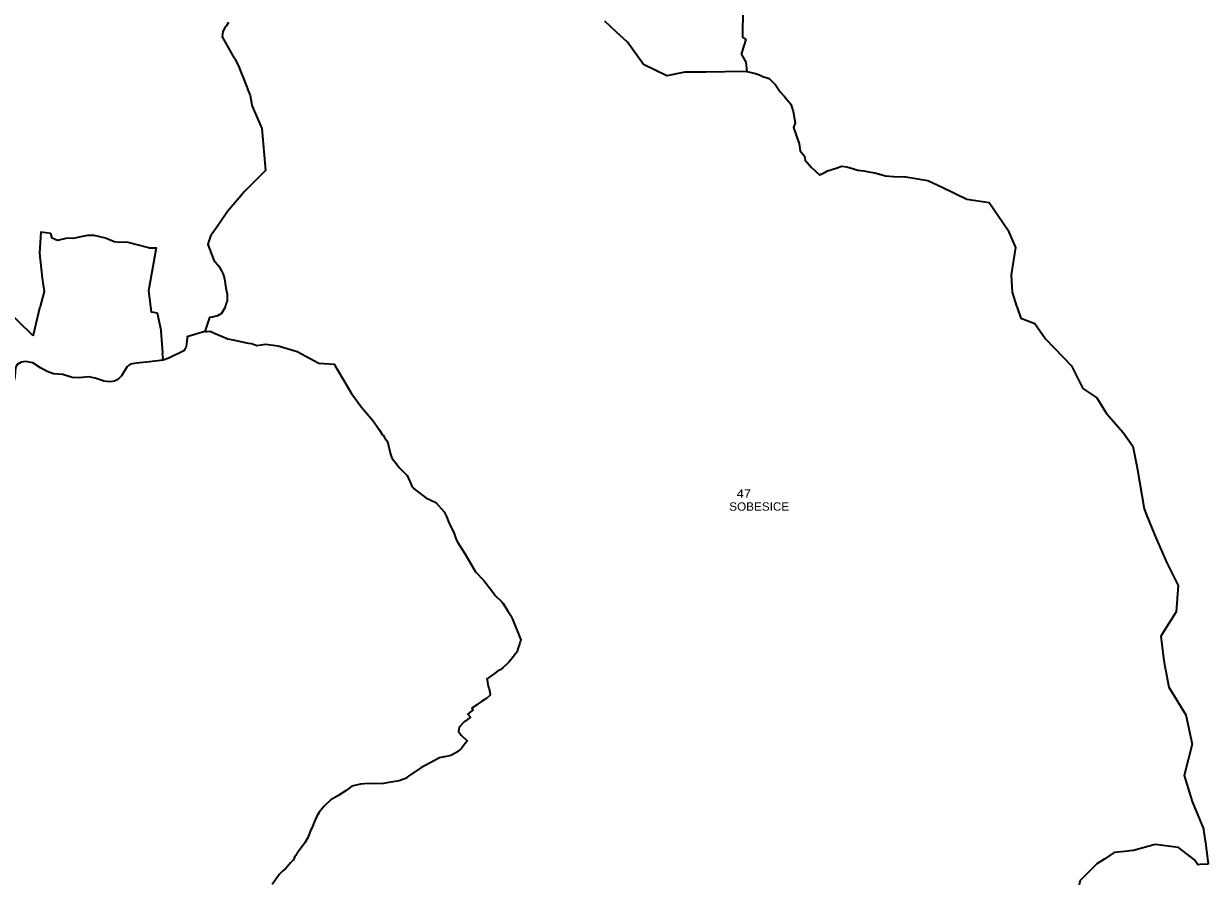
# Model space of a CAD drawing. Extents: x -610940 to -588976, y -1170376 to -1149800.
# Drawn here: x -598167 to -594623, y -1154902 to -1152351 of the extents above; entities that cross this region are included whole.
import ezdxf

# ---------------------------------------------------------------- set-up
doc = ezdxf.new("R2010")
doc.units = 0
doc.header["$LTSCALE"] = 10
doc.layers.add('54', color=7, linetype='Continuous', lineweight=35)
doc.layers.add('55', color=7, linetype='Continuous')
doc.layers.add('56', color=7, linetype='Continuous')

msp = doc.modelspace()

# ---------------------------------------------------------------- linework, layer by layer
at = {"layer": '54'}
for p, q in [((-598106.27, -1153152.22), (-598117.31, -1153197.4)), ((-598138.13, -1153282.6), (-598117.31, -1153197.4)), ((-598138.68, -1153284.83), (-598138.13, -1153282.6)), ((-597752.83, -1153338.08), (-597751.22, -1153349.79)), ((-597750.15, -1153357.57), (-597751.22, -1153349.79))]:
    msp.add_line(p, q, dxfattribs=at)
for points in [[(-596015.77, -1152305.6), (-596016.42, -1152391.27), (-596006.07, -1152398.68), (-596017.94, -1152436.65), (-596019.02, -1152439.81), (-596019.77, -1152443.4), (-596005.95, -1152466.61), (-596003.52, -1152494.58), (-596068.84, -1152495.06), (-596125.45, -1152495.82), (-596189.2, -1152496.63), (-596242.89, -1152507.33), (-596312.34, -1152473.24), (-596360.45, -1152406.2), (-596394.58, -1152375.26), (-596428.18, -1152343.88)], [(-597554.46, -1152347.09), (-597561.53, -1152358.53), (-597564.82, -1152363.84), (-597571.3, -1152374.31), (-597573.43, -1152390.4), (-597537.04, -1152454.25), (-597535.67, -1152456.67), (-597524.14, -1152477.31), (-597515.92, -1152498.31), (-597510.53, -1152512.06), (-597502.25, -1152533.21), (-597499.65, -1152539.87), (-597498.54, -1152542.68), (-597496.08, -1152548.98), (-597489.32, -1152566.23), (-597485.52, -1152588.28), (-597484.35, -1152595.14), (-597483.7, -1152597.78), (-597454.53, -1152664.27), (-597443.68, -1152790.87), (-597505.89, -1152852.62), (-597557.05, -1152912.73), (-597580.62, -1152946.74), (-597607.81, -1152986.56), (-597613.82, -1153005.03), (-597616.01, -1153011.86), (-597597.7, -1153058.74)], [(-596003.52, -1152494.58), (-595977.76, -1152500.16), (-595965.5, -1152504.52), (-595955.08, -1152509.58), (-595936.58, -1152514.66), (-595917.44, -1152533.82), (-595903.92, -1152555.48), (-595892.16, -1152567.64), (-595871.6, -1152591.92), (-595869.9, -1152597.7), (-595864.78, -1152614.14), (-595858.84, -1152647.78), (-595863.94, -1152661.92), (-595846.74, -1152710.98), (-595843.48, -1152731.8), (-595830.44, -1152747.62), (-595828.74, -1152759.98), (-595810.42, -1152781.02), (-595785.22, -1152803.96), (-595780.6, -1152801.4), (-595767.54, -1152794.02), (-595761.72, -1152790.92), (-595738.78, -1152783.96), (-595718.78, -1152777), (-595704.16, -1152779.84), (-595687.06, -1152784.2), (-595671.36, -1152789.26), (-595652.9, -1152791.06), (-595638.32, -1152794.76), (-595620.3, -1152797.16), (-595588.68, -1152806.1), (-595564.54, -1152808.78), (-595530.58, -1152809.5), (-595527.6, -1152809.82), (-595461.76, -1152820.26), (-595416.6, -1152840.9), (-595345.18, -1152876.14), (-595278.8, -1152885.94), (-595222.18, -1152968.33), (-595199.99, -1153021.25)], [(-597793.09, -1153021.92), (-597858.78, -1153004.63), (-597879.33, -1153006.04), (-597896.69, -1153004.13), (-597921.98, -1152992.94), (-597955.91, -1152985), (-597976.47, -1152984.72), (-598020.42, -1152993.75), (-598036.98, -1152993.06), (-598066.18, -1152999.88), (-598081.73, -1152992.62), (-598085.51, -1152978.76), (-598115.9, -1152974.94), (-598119.52, -1153038.03)], [(-598119.52, -1153038.03), (-598112.01, -1153113.03), (-598106.27, -1153152.22)], [(-597793.09, -1153021.92), (-597770.49, -1153021.36), (-597794.04, -1153150.2)], [(-595199.99, -1153021.25), (-595212.42, -1153102.38), (-595210.04, -1153154.18), (-595196.12, -1153196.52), (-595194.68, -1153200.5), (-595183.98, -1153232.74), (-595141.35, -1153247.94), (-595110.02, -1153294.1), (-595032.06, -1153374.88), (-595019.76, -1153399.22), (-594998.11, -1153442.37), (-594988.96, -1153448.84), (-594985.98, -1153450.76), (-594956.04, -1153470.7), (-594927.74, -1153517.4), (-594877.22, -1153574.7), (-594848.16, -1153615.24), (-594835.26, -1153680), (-594814.92, -1153802.58), (-594809.78, -1153815.58), (-594808.68, -1153818.42), (-594782.1, -1153884.74), (-594746.68, -1153964.64), (-594713.04, -1154032.5), (-594718.54, -1154110.96), (-594764.5, -1154183.75), (-594757, -1154249.24), (-594751.38, -1154280.6), (-594750.84, -1154283.64), (-594747.9, -1154299.2), (-594741.12, -1154336.37), (-594690.38, -1154418.8), (-594670.74, -1154507.01), (-594694.73, -1154601.21), (-594670.95, -1154678.66), (-594637.4, -1154760.24), (-594636.78, -1154763.08), (-594631.94, -1154796.18), (-594630.98, -1154801.12), (-594622.71, -1154865.58)], [(-597597.7, -1153058.74), (-597583.34, -1153077.07), (-597574.76, -1153090.52), (-597570.52, -1153100.56), (-597566.43, -1153114.14), (-597562.72, -1153142.17), (-597558.62, -1153160.17), (-597557.77, -1153181.44), (-597561.61, -1153186.99), (-597564.35, -1153199.22), (-597575.35, -1153217.89), (-597586.96, -1153225.77), (-597602.64, -1153228.96), (-597610.85, -1153230.14), (-597625.34, -1153272.57), (-597632.29, -1153274.6), (-597664.98, -1153284.15), (-597668.65, -1153285.21), (-597677.47, -1153287.77), (-597678.41, -1153295.55), (-597678.64, -1153297.43), (-597679.19, -1153302.27), (-597680.01, -1153309.36), (-597680.87, -1153316.94), (-597683.21, -1153321.34), (-597683.69, -1153322.23), (-597684.23, -1153323.22), (-597687.6, -1153329.58), (-597732.49, -1153351.48), (-597735.85, -1153352.58), (-597750.15, -1153357.57)], [(-597794.04, -1153150.2), (-597785.83, -1153213.41), (-597778.32, -1153214.54), (-597767.76, -1153216.17), (-597757.05, -1153267.11), (-597756.27, -1153270.8), (-597751.4, -1153336.21), (-597752.83, -1153338.08)], [(-598138.68, -1153284.83), (-598183.64, -1153241.04), (-598232.9, -1153191.43)], [(-597625.34, -1153272.57), (-597619.08, -1153272.16), (-597609.62, -1153271.59), (-597593.88, -1153278.21), (-597556.31, -1153294.07), (-597536.5, -1153298.19), (-597504.83, -1153304.71), (-597499.99, -1153305.67), (-597494.04, -1153306.67), (-597485.41, -1153308.06), (-597474.11, -1153312.15), (-597469.11, -1153314.02), (-597450.45, -1153310.99), (-597443.19, -1153309.78), (-597405.9, -1153315.29), (-597348.34, -1153332.31), (-597283.82, -1153367.34), (-597238.52, -1153369.85), (-597186.26, -1153457.81), (-597156.66, -1153498.92), (-597121.62, -1153539.81), (-597104.69, -1153564.41), (-597093.31, -1153581), (-597091.99, -1153582.79), (-597087.24, -1153589.75), (-597085.68, -1153592.13), (-597079.04, -1153601.48), (-597069.37, -1153639.51), (-597067.07, -1153648.43), (-597064.38, -1153651.87), (-597052.53, -1153667.37), (-597051.27, -1153669.07), (-597042.14, -1153680.99), (-597019.99, -1153703.47), (-597011.87, -1153721.21), (-597009.84, -1153725.5), (-597006.26, -1153733.3), (-596999.18, -1153742.67), (-596964.15, -1153770.13), (-596934.13, -1153783.94)], [(-597929.63, -1153420.15), (-597953.19, -1153411.6), (-597972.61, -1153408.03), (-598002.32, -1153411.31), (-598021.65, -1153409.35), (-598049.68, -1153401.31), (-598077.93, -1153399.17), (-598097.24, -1153392.34), (-598116.69, -1153380.62), (-598140.09, -1153366.01), (-598160.27, -1153362.42), (-598174.63, -1153363.77), (-598186.36, -1153370.45), (-598191.41, -1153379.44), (-598193.27, -1153407.64), (-598195.43, -1153418.01)], [(-597750.15, -1153357.57), (-597790.94, -1153363.13), (-597829.7, -1153366.55), (-597847.63, -1153370.28), (-597856.24, -1153376.29)], [(-597929.63, -1153420.15), (-597908.02, -1153421.87), (-597895.06, -1153420.21), (-597883.24, -1153413.4), (-597873.48, -1153404.15), (-597856.24, -1153376.29)], [(-596934.13, -1153783.94), (-596908.69, -1153811.45), (-596901.72, -1153826.2), (-596895.3, -1153843.71), (-596894.1, -1153845.89), (-596892.57, -1153848.78), (-596879.69, -1153873.75), (-596874.15, -1153891.61), (-596869.73, -1153900.48), (-596865.36, -1153908.46), (-596847.28, -1153936.38), (-596814.87, -1153991.8), (-596790.79, -1154017.15), (-596766.86, -1154048.36), (-596764.69, -1154051.11), (-596762.7, -1154053.45), (-596756.48, -1154061.78), (-596736.17, -1154080.85), (-596732.7, -1154086.35), (-596719.41, -1154107.08), (-596707.61, -1154125.36), (-596706.13, -1154128.84), (-596704.62, -1154132.91), (-596683.61, -1154184.91), (-596679.53, -1154194.88), (-596679.94, -1154196.11), (-596681.31, -1154200.19), (-596682.55, -1154204.41), (-596683.13, -1154206.1), (-596683.69, -1154207.74), (-596688.24, -1154222.04), (-596690.82, -1154230.61), (-596700.55, -1154242.9), (-596701.48, -1154244.08), (-596702.41, -1154245.26), (-596709.13, -1154254.31), (-596715.65, -1154261.95), (-596718.26, -1154264.28), (-596732.72, -1154277.18), (-596737.16, -1154281.12)], [(-596737.16, -1154281.12), (-596741.62, -1154284.13), (-596749.51, -1154288.92), (-596758.39, -1154295.63), (-596771.94, -1154305.36), (-596781.04, -1154311.58), (-596780.66, -1154314.19), (-596778.35, -1154328.29), (-596776.09, -1154335.98), (-596774.18, -1154341.8), (-596772.47, -1154351.22), (-596771.79, -1154360.57), (-596782.76, -1154369.99), (-596789.21, -1154374.04), (-596797.43, -1154378.93), (-596797.62, -1154379.08), (-596810.33, -1154388.45), (-596812.76, -1154390.21), (-596826.04, -1154399.75), (-596822.52, -1154404.2), (-596824.78, -1154406.12), (-596837.23, -1154416.21), (-596838.21, -1154416.88), (-596830.47, -1154426.21), (-596847.56, -1154439.08), (-596848.34, -1154439.5), (-596864.22, -1154455.85), (-596865.96, -1154469.29), (-596858.5, -1154479.92), (-596839.76, -1154497.37), (-596840.66, -1154498.47), (-596850.03, -1154509.58), (-596855.42, -1154516.83), (-596858.62, -1154521.07), (-596859.44, -1154522.23), (-596864.99, -1154526.2), (-596871.42, -1154530.66), (-596873.34, -1154532.06), (-596874.29, -1154532.87), (-596887.18, -1154539.62)], [(-596887.18, -1154539.62), (-596889.33, -1154540.61), (-596907.04, -1154544.62), (-596909.53, -1154545.21), (-596922.85, -1154548.25), (-596949.15, -1154562.31), (-596978.68, -1154577.92), (-597015.24, -1154602.83), (-597024.9, -1154609.64), (-597043.36, -1154616.55), (-597085.77, -1154624.01), (-597090.73, -1154624.3), (-597116.09, -1154625.79), (-597136.79, -1154624.29), (-597159.79, -1154626.67), (-597184.83, -1154632.55), (-597202.32, -1154645.9), (-597227.4, -1154661.48), (-597248.47, -1154673.97), (-597267.36, -1154691.99), (-597283.06, -1154710.77), (-597283.9, -1154712.37), (-597291.29, -1154724.52), (-597299.9, -1154745.55), (-597301.11, -1154748.35), (-597305.18, -1154758.58), (-597307.48, -1154763.03), (-597312.07, -1154773.63), (-597312.4, -1154774.38), (-597315.71, -1154784.45), (-597316.04, -1154785.44), (-597326.35, -1154802.36), (-597328.71, -1154806.23), (-597342.55, -1154824.87), (-597348.77, -1154833.37), (-597349.46, -1154834.43), (-597353.03, -1154839.73), (-597356.99, -1154845.6), (-597357.96, -1154847.65), (-597361.26, -1154854.66)], [(-594622.71, -1154865.58), (-594646.74, -1154867.4), (-594653.7, -1154868.08), (-594663.98, -1154853.48), (-594711.65, -1154816.59), (-594781.77, -1154806.74), (-594846.26, -1154824.79), (-594858.48, -1154826.3), (-594863.26, -1154826.82), (-594903.94, -1154831.02), (-594929.78, -1154848.3), (-594932.22, -1154849.74), (-594956.48, -1154865.5), (-595005.69, -1154915.44), (-595020.68, -1154974.54), (-595021.77, -1154976.36), (-595054.03, -1155029.88), (-595058.01, -1155036.7), (-595066.38, -1155058.3), (-595084.21, -1155104.14), (-595110.63, -1155170.57), (-595112.96, -1155176.16), (-595111.29, -1155193.92), (-595106.51, -1155248.2)], [(-597361.26, -1154854.66), (-597361.89, -1154855.26), (-597366.67, -1154859.81), (-597368.65, -1154862.21), (-597373.43, -1154868.01), (-597378.68, -1154874.17), (-597378.74, -1154874.25), (-597378.94, -1154874.49), (-597384.1, -1154879.71), (-597386.43, -1154881.61), (-597393.18, -1154887.09), (-597401.83, -1154896.17), (-597424.1, -1154926.78)]]:
    msp.add_lwpolyline(points, dxfattribs=at)

# ---------------------------------------------------------------- texts
at = {"layer": '55', "width": 1.05}
msp.add_text('SOBESICE ', height=25, dxfattribs=at).set_placement((-596056.08, -1153808.37))
at = {"layer": '56', "width": 1.15}
msp.add_text('47 ', height=25, dxfattribs=at).set_placement((-596033.74, -1153769.69))

doc.saveas('drawing.dxf')
